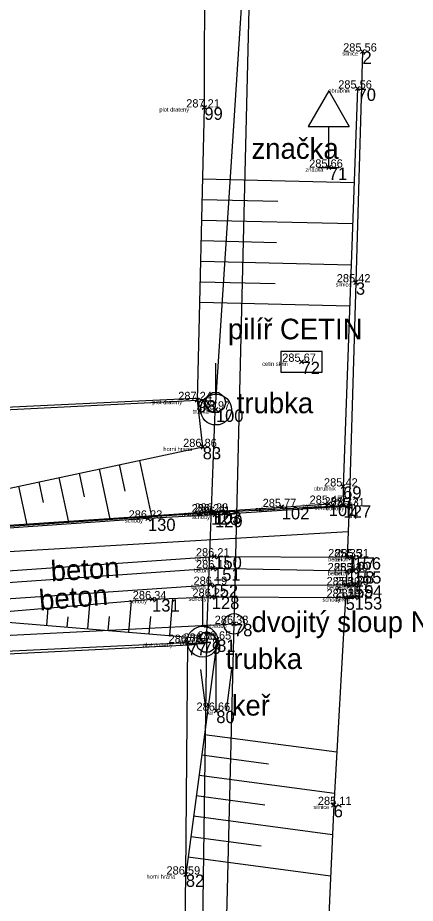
# Model space of a CAD drawing. Extents: x -456675 to -456278, y -1112395 to -1112217.
# Drawn here: x -456568.22 to -456558.57, y -1112310.75 to -1112289.23 of the extents above; entities that cross this region are included whole.
import ezdxf

# ---------------------------------------------------------------- set-up
doc = ezdxf.new("R2010")
doc.units = 0
for name, color, linetype in [('Cislo_bodu', 7, 'Continuous'), ('g_beton', 7, 'Continuous'), ('g_CETIN', 7, 'Continuous'), ('g_dopravni_znaceni', 7, 'Continuous'), ('g_elektrina', 7, 'Continuous'), ('g_katastr_stabilizace', 7, 'Continuous'), ('g_komunikace', 7, 'Continuous'), ('g_obrubnik', 7, 'Continuous'), ('g_ploty', 7, 'Continuous'), ('g_schody', 7, 'Continuous'), ('g_terenni_hrany', 7, 'Continuous'), ('g_vegetace', 7, 'Continuous'), ('g_zabradli', 7, 'Continuous'), ('Katastralni_mapa', 7, 'Continuous'), ('Kod_bodu', 7, 'Continuous'), ('Vyska_bodu', 7, 'Continuous'), ('Znacka_bodu', 7, 'Continuous')]:
    doc.layers.add(name, color=color, linetype=linetype)

msp = doc.modelspace()

# ---------------------------------------------------------------- linework, layer by layer
at = {"layer": 'g_beton'}
for points in [[(-456575.29, -1112303.14), (-456572.7, -1112302.97), (-456571.04, -1112302.85), (-456563.45, -1112302.32), (-456560.22, -1112302.34)], [(-456560.23, -1112302.68), (-456563.48, -1112302.61), (-456571.03, -1112303.14), (-456572.7, -1112303.27), (-456575.29, -1112303.43)], [(-456575.28, -1112303.79), (-456572.69, -1112303.66), (-456571, -1112303.52), (-456563.54, -1112303.01), (-456560.25, -1112303.02)]]:
    msp.add_lwpolyline(points, dxfattribs=at)
at = {"layer": 'g_CETIN'}
msp.add_lwpolyline([(-456561.83, -1112297.84), (-456560.83, -1112297.84), (-456560.83, -1112297.34), (-456561.83, -1112297.34)], close=True, dxfattribs=at)
at = {"layer": 'g_dopravni_znaceni'}
for p, q in [((-456560.67, -1112291.004), (-456561.17, -1112291.87)), ((-456560.67, -1112291.004), (-456560.17, -1112291.87)), ((-456561.17, -1112291.87), (-456560.17, -1112291.87)), ((-456560.67, -1112292.87), (-456560.67, -1112291.87)), ((-456560.92, -1112292.87), (-456560.42, -1112292.87))]:
    msp.add_line(p, q, dxfattribs=at)
at = {"layer": 'g_elektrina'}
msp.add_line((-456591.85, -1112305.42), (-456562.97, -1112303.96), dxfattribs=at)
msp.add_lwpolyline([(-456563.36, -1112319.78), (-456562.97, -1112303.96), (-456562.3, -1112276.72)], dxfattribs=at)
msp.add_circle((-456562.97, -1112303.96), 0.25, dxfattribs=at)
at = {"layer": 'g_katastr_stabilizace'}
for p, q in [((-456563.41, -1112298.376), (-456563.41, -1112297.626)), ((-456563.73, -1112304.015), (-456563.73, -1112303.265))]:
    msp.add_line(p, q, dxfattribs=at)
for centre, radius in [((-456563.41, -1112298.751), 0.375), ((-456563.41, -1112298.751), 0.0005), ((-456563.73, -1112304.39), 0.375), ((-456563.73, -1112304.39), 0.0005)]:
    msp.add_circle(centre, radius, dxfattribs=at)
at = {"layer": 'g_komunikace'}
msp.add_lwpolyline([(-456559.85, -1112290.05), (-456560.01, -1112295.66), (-456560.17, -1112301.1), (-456560.22, -1112302.34), (-456560.07, -1112302.34), (-456560.06, -1112302.68), (-456560.23, -1112302.68), (-456560.25, -1112303.02), (-456560.04, -1112303.02), (-456560.04, -1112303.31), (-456560.26, -1112303.32), (-456560.55, -1112308.36), (-456560.86, -1112315.33)], dxfattribs=at)
at = {"layer": 'g_obrubnik'}
for p, q in [((-456559.97, -1112290.95), (-456560.32, -1112300.62)), ((-456560.32, -1112300.62), (-456560.31, -1112301.08))]:
    msp.add_line(p, q, dxfattribs=at)
msp.add_lwpolyline([(-456578.33, -1112302.26), (-456575.08, -1112302.04), (-456563.53, -1112301.25), (-456560.31, -1112301.08)], dxfattribs=at)
at = {"layer": 'g_ploty'}
for points in [[(-456588.66, -1112299.7), (-456577.12, -1112299.18), (-456570.18, -1112298.84), (-456563.86, -1112298.52), (-456563.69, -1112291.41), (-456563.68, -1112287.66)], [(-456564.24, -1112317.5), (-456564.14, -1112310.05), (-456564.09, -1112304.42), (-456570.24, -1112304.71), (-456578.76, -1112305.1), (-456590.32, -1112305.79)]]:
    msp.add_lwpolyline(points, dxfattribs=at)
at = {"layer": 'g_schody'}
msp.add_line((-456560.195, -1112301.72), (-456575.325, -1112302.62), dxfattribs=at)
msp.add_lwpolyline([(-456560.17, -1112301.1), (-456563.43, -1112301.31), (-456565.06, -1112301.4), (-456571.12, -1112301.82), (-456572.8, -1112301.93), (-456575.36, -1112302.1), (-456575.29, -1112303.14), (-456575.29, -1112303.43), (-456575.28, -1112303.79), (-456575.3, -1112304.12), (-456572.7, -1112303.96), (-456570.99, -1112303.85), (-456570.03, -1112303.79), (-456564.96, -1112303.36), (-456563.51, -1112303.3), (-456560.26, -1112303.32)], dxfattribs=at)
at = {"layer": 'g_terenni_hrany'}
for p, q in [((-456560.053, -1112293.241), (-456563.732, -1112293.153)), ((-456561.907, -1112293.697), (-456563.744, -1112293.653)), ((-456560.089, -1112294.24), (-456563.756, -1112294.153)), ((-456561.937, -1112294.696), (-456563.768, -1112294.653)), ((-456560.125, -1112295.24), (-456563.779, -1112295.152)), ((-456561.967, -1112295.696), (-456563.791, -1112295.652)), ((-456560.161, -1112296.239), (-456563.803, -1112296.152)), ((-456564.969, -1112301.348), (-456565.259, -1112299.986)), ((-456565.976, -1112301.417), (-456566.237, -1112300.194)), ((-456565.61, -1112300.736), (-456565.748, -1112300.09)), ((-456566.984, -1112301.486), (-456567.215, -1112300.402)), ((-456566.603, -1112300.875), (-456566.726, -1112300.298)), ((-456567.992, -1112301.555), (-456568.193, -1112300.61)), ((-456567.596, -1112301.013), (-456567.704, -1112300.506)), ((-456565.471, -1112303.403), (-456565.534, -1112304.162)), ((-456564.462, -1112303.339), (-456564.537, -1112304.244)), ((-456567.492, -1112303.575), (-456567.527, -1112303.997)), ((-456566.481, -1112303.489), (-456566.53, -1112304.079)), ((-456567.008, -1112303.785), (-456567.028, -1112304.038)), ((-456566.004, -1112303.783), (-456566.032, -1112304.121)), ((-456565, -1112303.782), (-456565.035, -1112304.203)), ((-456560.476, -1112307.08), (-456563.688, -1112306.653)), ((-456562.13, -1112307.365), (-456563.754, -1112307.149)), ((-456560.534, -1112308.082), (-456563.82, -1112307.644)), ((-456562.223, -1112308.361), (-456563.886, -1112308.14)), ((-456560.582, -1112309.084), (-456563.952, -1112308.636)), ((-456562.311, -1112309.358), (-456564.018, -1112309.131)), ((-456560.627, -1112310.087), (-456564.084, -1112309.627))]:
    msp.add_line(p, q, dxfattribs=at)
for points in [[(-456572.82, -1112301.85), (-456568.99, -1112300.78), (-456563.73, -1112299.66), (-456563.86, -1112298.52)], [(-456570.03, -1112303.79), (-456563.38, -1112304.34), (-456564.14, -1112310.05)]]:
    msp.add_lwpolyline(points, dxfattribs=at)
at = {"layer": 'g_vegetace'}
for p, q in [((-456563.4, -1112306.07), (-456563.4, -1112304.57)), ((-456563.65, -1112306.07), (-456563.775, -1112305.07)), ((-456563.15, -1112306.07), (-456563.025, -1112305.07))]:
    msp.add_line(p, q, dxfattribs=at)
at = {"layer": 'g_zabradli'}
msp.add_lwpolyline([(-456575.41, -1112302.04), (-456572.82, -1112301.85), (-456563.46, -1112301.23), (-456561.81, -1112301.12), (-456560.67, -1112301.04)], dxfattribs=at)
at = {"layer": 'Katastralni_mapa'}
for points in [[(-456562.71, -1112287.61), (-456563.42, -1112298.58)], [(-456563.92, -1112298.48), (-456593.04, -1112299.87)], [(-456563.42, -1112298.58), (-456563.92, -1112298.48)], [(-456563.64, -1112304.41), (-456563.42, -1112298.58)], [(-456563.445, -1112298.58), (-456563.395, -1112298.58)], [(-456578.75, -1112305.2), (-456564.06, -1112304.47)], [(-456564.06, -1112304.47), (-456563.64, -1112304.41)], [(-456563.64, -1112304.41), (-456564.02, -1112331.27)], [(-456563.665, -1112304.41), (-456563.615, -1112304.41)]]:
    msp.add_lwpolyline(points, dxfattribs=at)
for points in [[(-456563.345, -1112298.34), (-456563.22, -1112298.435), (-456563.17, -1112298.58), (-456563.22, -1112298.725), (-456563.345, -1112298.82), (-456563.495, -1112298.82), (-456563.62, -1112298.725), (-456563.67, -1112298.58), (-456563.62, -1112298.435), (-456563.495, -1112298.34)], [(-456563.565, -1112304.17), (-456563.44, -1112304.265), (-456563.39, -1112304.41), (-456563.44, -1112304.555), (-456563.565, -1112304.65), (-456563.715, -1112304.65), (-456563.84, -1112304.555), (-456563.89, -1112304.41), (-456563.84, -1112304.265), (-456563.715, -1112304.17)]]:
    msp.add_lwpolyline(points, close=True, dxfattribs=at)
at = {"layer": 'Znacka_bodu'}
for p, q in [((-456559.85, -1112290.05), (-456559.9, -1112290)), ((-456559.85, -1112290.05), (-456559.9, -1112290.1)), ((-456559.85, -1112290.05), (-456559.8, -1112290)), ((-456559.85, -1112290.05), (-456559.8, -1112290.1)), ((-456559.97, -1112290.95), (-456560.02, -1112290.9)), ((-456559.97, -1112290.95), (-456560.02, -1112291)), ((-456559.97, -1112290.95), (-456559.92, -1112290.9)), ((-456559.97, -1112290.95), (-456559.92, -1112291)), ((-456563.69, -1112291.41), (-456563.74, -1112291.36)), ((-456563.69, -1112291.41), (-456563.74, -1112291.46)), ((-456563.69, -1112291.41), (-456563.64, -1112291.36)), ((-456563.69, -1112291.41), (-456563.64, -1112291.46)), ((-456560.67, -1112292.87), (-456560.72, -1112292.82)), ((-456560.67, -1112292.87), (-456560.72, -1112292.92)), ((-456560.67, -1112292.87), (-456560.62, -1112292.82)), ((-456560.67, -1112292.87), (-456560.62, -1112292.92)), ((-456560.01, -1112295.66), (-456560.06, -1112295.61)), ((-456560.01, -1112295.66), (-456560.06, -1112295.71)), ((-456560.01, -1112295.66), (-456559.96, -1112295.61)), ((-456560.01, -1112295.66), (-456559.96, -1112295.71)), ((-456561.33, -1112297.59), (-456561.38, -1112297.54)), ((-456561.33, -1112297.59), (-456561.38, -1112297.64)), ((-456561.33, -1112297.59), (-456561.28, -1112297.54)), ((-456561.33, -1112297.59), (-456561.28, -1112297.64)), ((-456563.86, -1112298.52), (-456563.91, -1112298.47)), ((-456563.86, -1112298.52), (-456563.81, -1112298.47)), ((-456563.86, -1112298.52), (-456563.91, -1112298.57)), ((-456563.86, -1112298.52), (-456563.81, -1112298.57)), ((-456563.41, -1112298.75), (-456563.46, -1112298.7)), ((-456563.41, -1112298.75), (-456563.36, -1112298.7)), ((-456563.41, -1112298.75), (-456563.46, -1112298.8)), ((-456563.41, -1112298.75), (-456563.36, -1112298.8)), ((-456563.73, -1112299.66), (-456563.78, -1112299.61)), ((-456563.73, -1112299.66), (-456563.78, -1112299.71)), ((-456563.73, -1112299.66), (-456563.68, -1112299.61)), ((-456563.73, -1112299.66), (-456563.68, -1112299.71)), ((-456560.32, -1112300.62), (-456560.37, -1112300.57)), ((-456560.32, -1112300.62), (-456560.37, -1112300.67)), ((-456560.32, -1112300.62), (-456560.27, -1112300.57)), ((-456560.32, -1112300.62), (-456560.27, -1112300.67)), ((-456561.81, -1112301.12), (-456561.86, -1112301.07)), ((-456561.81, -1112301.12), (-456561.76, -1112301.07)), ((-456560.67, -1112301.04), (-456560.72, -1112300.99)), ((-456560.67, -1112301.04), (-456560.72, -1112301.09)), ((-456560.67, -1112301.04), (-456560.62, -1112300.99)), ((-456560.67, -1112301.04), (-456560.62, -1112301.09)), ((-456560.31, -1112301.08), (-456560.36, -1112301.03)), ((-456560.31, -1112301.08), (-456560.36, -1112301.13)), ((-456560.31, -1112301.08), (-456560.26, -1112301.03)), ((-456560.31, -1112301.08), (-456560.26, -1112301.13)), ((-456560.17, -1112301.1), (-456560.22, -1112301.05)), ((-456560.17, -1112301.1), (-456560.12, -1112301.05)), ((-456563.53, -1112301.25), (-456563.58, -1112301.2)), ((-456563.53, -1112301.25), (-456563.58, -1112301.3)), ((-456563.53, -1112301.25), (-456563.48, -1112301.2)), ((-456563.53, -1112301.25), (-456563.48, -1112301.3)), ((-456563.46, -1112301.23), (-456563.51, -1112301.18)), ((-456563.46, -1112301.23), (-456563.51, -1112301.28)), ((-456563.43, -1112301.31), (-456563.48, -1112301.26)), ((-456563.43, -1112301.31), (-456563.48, -1112301.36)), ((-456563.46, -1112301.23), (-456563.41, -1112301.18)), ((-456563.46, -1112301.23), (-456563.41, -1112301.28)), ((-456563.43, -1112301.31), (-456563.38, -1112301.26)), ((-456563.43, -1112301.31), (-456563.38, -1112301.36)), ((-456561.81, -1112301.12), (-456561.86, -1112301.17)), ((-456561.81, -1112301.12), (-456561.76, -1112301.17)), ((-456560.17, -1112301.1), (-456560.22, -1112301.15)), ((-456560.17, -1112301.1), (-456560.12, -1112301.15)), ((-456565.06, -1112301.4), (-456565.11, -1112301.35)), ((-456565.06, -1112301.4), (-456565.11, -1112301.45)), ((-456565.06, -1112301.4), (-456565.01, -1112301.35)), ((-456565.06, -1112301.4), (-456565.01, -1112301.45)), ((-456563.45, -1112302.32), (-456563.5, -1112302.27)), ((-456563.45, -1112302.32), (-456563.5, -1112302.37)), ((-456563.45, -1112302.32), (-456563.4, -1112302.27)), ((-456563.45, -1112302.32), (-456563.4, -1112302.37)), ((-456560.22, -1112302.34), (-456560.27, -1112302.29)), ((-456560.22, -1112302.34), (-456560.27, -1112302.39)), ((-456560.22, -1112302.34), (-456560.17, -1112302.29)), ((-456560.22, -1112302.34), (-456560.17, -1112302.39)), ((-456560.07, -1112302.34), (-456560.12, -1112302.29)), ((-456560.07, -1112302.34), (-456560.12, -1112302.39)), ((-456560.07, -1112302.34), (-456560.02, -1112302.29)), ((-456560.07, -1112302.34), (-456560.02, -1112302.39)), ((-456563.48, -1112302.61), (-456563.53, -1112302.56)), ((-456563.48, -1112302.61), (-456563.43, -1112302.56)), ((-456563.48, -1112302.61), (-456563.53, -1112302.66)), ((-456563.48, -1112302.61), (-456563.43, -1112302.66)), ((-456560.23, -1112302.68), (-456560.28, -1112302.63)), ((-456560.23, -1112302.68), (-456560.28, -1112302.73)), ((-456560.23, -1112302.68), (-456560.18, -1112302.63)), ((-456560.23, -1112302.68), (-456560.18, -1112302.73)), ((-456560.06, -1112302.68), (-456560.11, -1112302.63)), ((-456560.06, -1112302.68), (-456560.11, -1112302.73)), ((-456560.06, -1112302.68), (-456560.01, -1112302.63)), ((-456560.06, -1112302.68), (-456560.01, -1112302.73)), ((-456563.54, -1112303.01), (-456563.59, -1112302.96)), ((-456563.54, -1112303.01), (-456563.59, -1112303.06)), ((-456563.54, -1112303.01), (-456563.49, -1112302.96)), ((-456563.54, -1112303.01), (-456563.49, -1112303.06)), ((-456560.25, -1112303.02), (-456560.3, -1112302.97)), ((-456560.25, -1112303.02), (-456560.3, -1112303.07)), ((-456560.25, -1112303.02), (-456560.2, -1112302.97)), ((-456560.25, -1112303.02), (-456560.2, -1112303.07)), ((-456560.04, -1112303.02), (-456560.09, -1112302.97)), ((-456560.04, -1112303.02), (-456560.09, -1112303.07)), ((-456560.04, -1112303.02), (-456559.99, -1112302.97)), ((-456560.04, -1112303.02), (-456559.99, -1112303.07)), ((-456563.51, -1112303.3), (-456563.56, -1112303.25)), ((-456563.51, -1112303.3), (-456563.46, -1112303.25)), ((-456564.96, -1112303.36), (-456565.01, -1112303.31)), ((-456564.96, -1112303.36), (-456565.01, -1112303.41)), ((-456564.96, -1112303.36), (-456564.91, -1112303.31)), ((-456564.96, -1112303.36), (-456564.91, -1112303.41)), ((-456563.51, -1112303.3), (-456563.56, -1112303.35)), ((-456563.51, -1112303.3), (-456563.46, -1112303.35)), ((-456560.26, -1112303.32), (-456560.31, -1112303.27)), ((-456560.26, -1112303.32), (-456560.31, -1112303.37)), ((-456560.26, -1112303.32), (-456560.21, -1112303.27)), ((-456560.26, -1112303.32), (-456560.21, -1112303.37)), ((-456560.04, -1112303.31), (-456560.09, -1112303.26)), ((-456560.04, -1112303.31), (-456560.09, -1112303.36)), ((-456560.04, -1112303.31), (-456559.99, -1112303.26)), ((-456560.04, -1112303.31), (-456559.99, -1112303.36)), ((-456562.97, -1112303.96), (-456563.02, -1112303.91)), ((-456562.97, -1112303.96), (-456563.02, -1112304.01)), ((-456562.97, -1112303.96), (-456562.92, -1112303.91)), ((-456562.97, -1112303.96), (-456562.92, -1112304.01)), ((-456563.38, -1112304.34), (-456563.43, -1112304.29)), ((-456563.38, -1112304.34), (-456563.33, -1112304.29)), ((-456564.09, -1112304.42), (-456564.14, -1112304.37)), ((-456564.09, -1112304.42), (-456564.14, -1112304.47)), ((-456564.09, -1112304.42), (-456564.04, -1112304.37)), ((-456564.09, -1112304.42), (-456564.04, -1112304.47)), ((-456563.73, -1112304.39), (-456563.78, -1112304.34)), ((-456563.73, -1112304.39), (-456563.78, -1112304.44)), ((-456563.73, -1112304.39), (-456563.68, -1112304.34)), ((-456563.73, -1112304.39), (-456563.68, -1112304.44)), ((-456563.38, -1112304.34), (-456563.43, -1112304.39)), ((-456563.38, -1112304.34), (-456563.33, -1112304.39)), ((-456563.4, -1112306.07), (-456563.45, -1112306.02)), ((-456563.4, -1112306.07), (-456563.35, -1112306.02)), ((-456563.4, -1112306.07), (-456563.45, -1112306.12)), ((-456563.4, -1112306.07), (-456563.35, -1112306.12)), ((-456560.55, -1112308.36), (-456560.6, -1112308.31)), ((-456560.55, -1112308.36), (-456560.6, -1112308.41)), ((-456560.55, -1112308.36), (-456560.5, -1112308.31)), ((-456560.55, -1112308.36), (-456560.5, -1112308.41)), ((-456564.14, -1112310.05), (-456564.19, -1112310)), ((-456564.14, -1112310.05), (-456564.19, -1112310.1)), ((-456564.14, -1112310.05), (-456564.09, -1112310)), ((-456564.14, -1112310.05), (-456564.09, -1112310.1))]:
    msp.add_line(p, q, dxfattribs=at)

# ---------------------------------------------------------------- texts
at = {"layer": 'Cislo_bodu'}
for s, p in [('2', (-456559.85, -1112290.35)), ('70', (-456559.97, -1112291.25)), ('99', (-456563.69, -1112291.71)), ('71', (-456560.67, -1112293.17)), ('3', (-456560.01, -1112295.96)), ('72', (-456561.33, -1112297.89)), ('98', (-456563.86, -1112298.82)), ('100', (-456563.41, -1112299.05)), ('83', (-456563.73, -1112299.96)), ('69', (-456560.32, -1112300.92)), ('101', (-456560.67, -1112301.34)), ('127', (-456560.31, -1112301.38)), ('126', (-456563.53, -1112301.55)), ('103', (-456563.46, -1112301.53)), ('129', (-456563.43, -1112301.61)), ('102', (-456561.81, -1112301.42)), ('4', (-456560.17, -1112301.4)), ('130', (-456565.06, -1112301.7)), ('150', (-456563.45, -1112302.62)), ('157', (-456560.22, -1112302.64)), ('156', (-456560.07, -1112302.64)), ('151', (-456563.48, -1112302.91)), ('158', (-456560.23, -1112302.98)), ('155', (-456560.06, -1112302.98)), ('152', (-456563.54, -1112303.31)), ('159', (-456560.25, -1112303.32)), ('154', (-456560.04, -1112303.32)), ('131', (-456564.96, -1112303.66)), ('128', (-456563.51, -1112303.6)), ('5', (-456560.26, -1112303.62)), ('153', (-456560.04, -1112303.61)), ('78', (-456562.97, -1112304.26)), ('77', (-456564.09, -1112304.72)), ('79', (-456563.73, -1112304.69)), ('81', (-456563.38, -1112304.64)), ('80', (-456563.4, -1112306.37)), ('6', (-456560.55, -1112308.66)), ('82', (-456564.14, -1112310.35))]:
    msp.add_text(s, height=0.3, dxfattribs=at).set_placement(p)
at = {"layer": 'g_beton'}
for rotation, p in [(3.2894, (-456567.409, -1112302.926)), (4.8107, (-456567.684, -1112303.634))]:
    msp.add_text('beton', height=0.5, rotation=rotation, dxfattribs=at).set_placement(p)
at = {"layer": 'g_CETIN'}
msp.add_text('pilíř CETIN', height=0.5, dxfattribs=at).set_placement((-456563.118, -1112297.043))
at = {"layer": 'g_dopravni_znaceni'}
msp.add_text('značka', height=0.5, dxfattribs=at).set_placement((-456562.546, -1112292.658))
at = {"layer": 'g_elektrina'}
msp.add_text('dvojitý sloup NN', height=0.5, dxfattribs=at).set_placement((-456562.546, -1112304.158))
at = {"layer": 'g_katastr_stabilizace'}
for p in [(-456562.905, -1112298.84), (-456563.174, -1112305.055)]:
    msp.add_text('trubka', height=0.5, dxfattribs=at).set_placement(p)
at = {"layer": 'g_vegetace'}
msp.add_text('keř', height=0.5, dxfattribs=at).set_placement((-456563.027, -1112306.188))
at = {"layer": 'Kod_bodu'}
for s, p in [('silnice', (-456560.341, -1112290.15)), ('obrubnik', (-456560.68, -1112291.05)), ('plot drateny', (-456564.783, -1112291.51)), ('znacka', (-456561.237, -1112292.97)), ('silnice', (-456560.501, -1112295.76)), ('cetin skrin', (-456562.285, -1112297.69)), ('plot drateny', (-456564.953, -1112298.62)), ('trubka', (-456563.971, -1112298.85)), ('horni hrana', (-456564.686, -1112299.76)), ('obrubnik', (-456561.03, -1112300.72)), ('zabradli', (-456561.312, -1112301.14)), ('obrubnik', (-456561.02, -1112301.18)), ('schody', (-456560.732, -1112301.2)), ('obrubnik', (-456564.24, -1112301.35)), ('zabradli', (-456564.102, -1112301.33)), ('schody', (-456563.992, -1112301.41)), ('zabradli', (-456562.452, -1112301.22)), ('schody', (-456565.622, -1112301.5)), ('beton', (-456563.915, -1112302.42)), ('beton', (-456560.685, -1112302.44)), ('beton', (-456560.535, -1112302.44)), ('beton', (-456563.945, -1112302.71)), ('beton', (-456560.695, -1112302.78)), ('beton', (-456560.525, -1112302.78)), ('beton', (-456564.005, -1112303.11)), ('beton', (-456560.715, -1112303.12)), ('beton', (-456560.505, -1112303.12)), ('schody', (-456565.522, -1112303.46)), ('schody', (-456564.072, -1112303.4)), ('schody', (-456560.822, -1112303.42)), ('beton', (-456560.505, -1112303.41)), ('bet.sloup', (-456563.71, -1112304.06)), ('plot drateny', (-456565.183, -1112304.52)), ('horni hrana', (-456564.336, -1112304.44)), ('trubka', (-456564.291, -1112304.49)), ('ker', (-456563.667, -1112306.17)), ('silnice', (-456561.041, -1112308.46)), ('horni hrana', (-456565.096, -1112310.15))]:
    msp.add_text(s, height=0.1, dxfattribs=at).set_placement(p)
at = {"layer": 'Vyska_bodu'}
for s, p in [('285.56', (-456560.32, -1112290.05)), ('285.56', (-456560.44, -1112290.95)), ('287.21', (-456564.131, -1112291.41)), ('285.66', (-456561.146, -1112292.87)), ('285.42', (-456560.475, -1112295.66)), ('285.67', (-456561.8, -1112297.59)), ('287.24', (-456564.325, -1112298.52)), ('286.97', (-456563.881, -1112298.75)), ('286.86', (-456564.206, -1112299.66)), ('285.42', (-456560.785, -1112300.62)), ('285.47', (-456561.135, -1112301.04)), ('285.37', (-456560.775, -1112301.08)), ('286.24', (-456564, -1112301.25)), ('286.23', (-456563.93, -1112301.23)), ('285.77', (-456562.275, -1112301.12)), ('285.31', (-456560.611, -1112301.1)), ('286.23', (-456565.53, -1112301.4)), ('286.21', (-456563.876, -1112301.31)), ('286.21', (-456563.896, -1112302.32)), ('285.35', (-456560.685, -1112302.34)), ('285.31', (-456560.511, -1112302.34)), ('286.18', (-456563.893, -1112302.61)), ('285.34', (-456560.695, -1112302.68)), ('285.30', (-456560.533, -1112302.68)), ('286.19', (-456563.954, -1112303.01)), ('285.30', (-456560.723, -1112303.02)), ('285.30', (-456560.513, -1112303.02)), ('286.34', (-456565.43, -1112303.36)), ('286.22', (-456563.98, -1112303.3)), ('285.28', (-456560.725, -1112303.32)), ('285.27', (-456560.505, -1112303.31)), ('286.38', (-456563.44, -1112303.96)), ('286.78', (-456564.56, -1112304.42)), ('286.77', (-456564.2, -1112304.39)), ('286.65', (-456563.856, -1112304.34)), ('286.66', (-456563.881, -1112306.07)), ('285.11', (-456560.934, -1112308.36)), ('286.59', (-456564.611, -1112310.05))]:
    msp.add_text(s, height=0.2, dxfattribs=at).set_placement(p)

doc.saveas('drawing.dxf')
